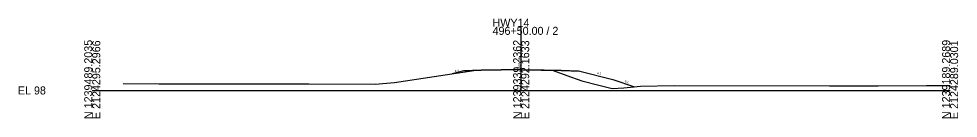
# Model space of a CAD drawing. Extents: x -26 to 303, y -10 to 11521.
# Drawn here: x -25.7 to 302.8, y 7990.3 to 8025 of the extents above; entities that cross this region are included whole.
import ezdxf

# ---------------------------------------------------------------- set-up
doc = ezdxf.new("R2010")
doc.units = 0
for name, color, linetype in [('XS_CELL', 7, 'Continuous'), ('XS_P_FINISHED_GRADE', 7, 'Continuous'), ('XS_P_SUBGRADE_GRANULAR', 7, 'Continuous'), ('XS_P_SUBGRADE_LEVELING', 7, 'Continuous'), ('XS_P_TX_FS_BS', 7, 'Continuous'), ('XS_X_GROUND', 7, 'Continuous'), ('XS_X_GROUND_TX', 7, 'Continuous')]:
    doc.layers.add(name, color=color, linetype=linetype)

msp = doc.modelspace()

# ---------------------------------------------------------------- linework, layer by layer
at = {"layer": 'XS_CELL'}
for p, q in [((150, 8000), (150, 8022.23)), ((0, 8000), (150, 8000)), ((150, 8000), (300, 8000))]:
    msp.add_line(p, q, dxfattribs=at)
at = {"layer": 'XS_P_FINISHED_GRADE'}
for p, q in [((130, 8006.83), (125.81, 8005.79)), ((136, 8007.07), (130, 8006.83)), ((150, 8007.35), (136, 8007.07)), ((150, 8007.35), (164, 8007.07)), ((164, 8007.07), (170, 8006.83)), ((170, 8006.83), (182, 8003.83)), ((182, 8003.83), (189.69, 8001.27))]:
    msp.add_line(p, q, dxfattribs=at)
at = {"layer": 'XS_P_SUBGRADE_GRANULAR'}
for p, q in [((136, 8006.95), (129.4, 8006.69)), ((164, 8006.95), (170.6, 8006.69))]:
    msp.add_line(p, q, dxfattribs=at)
at = {"layer": 'XS_P_SUBGRADE_LEVELING'}
for p, q in [((150, 8007.23), (136, 8006.95)), ((136, 8006.95), (136, 8007.07)), ((150, 8007.23), (164, 8006.95)), ((164, 8006.95), (164, 8007.07))]:
    msp.add_line(p, q, dxfattribs=at)
at = {"layer": 'XS_X_GROUND'}
for p, q in [((105.7, 8002.78), (133.49, 8006.93)), ((133.49, 8006.93), (136.11, 8007.16)), ((136.11, 8007.16), (138.86, 8007.22)), ((138.86, 8007.22), (147.66, 8007.41)), ((147.66, 8007.41), (150, 8007.35)), ((150, 8007.35), (156.52, 8007.2)), ((156.52, 8007.2), (158.09, 8007.15)), ((158.09, 8007.15), (158.6, 8007.11)), ((158.6, 8007.11), (161.18, 8006.94)), ((161.18, 8006.94), (166.02, 8005.26)), ((166.02, 8005.26), (171.24, 8003.41)), ((171.24, 8003.41), (177.13, 8001.82)), ((10.81, 8002.38), (23.3, 8002.34)), ((23.3, 8002.34), (26.44, 8002.32)), ((26.44, 8002.32), (47.26, 8002.35)), ((47.26, 8002.35), (75.73, 8002.31)), ((75.73, 8002.31), (98.97, 8002.21)), ((98.97, 8002.21), (105.7, 8002.78)), ((177.13, 8001.82), (181.8, 8000.64)), ((181.8, 8000.64), (185.96, 8000.95)), ((185.96, 8000.95), (191.71, 8001.44)), ((191.71, 8001.44), (203.52, 8001.72)), ((203.52, 8001.72), (257.79, 8001.6)), ((257.79, 8001.6), (274.82, 8001.65)), ((274.82, 8001.65), (291.75, 8001.71)), ((291.75, 8001.71), (300, 8001.7))]:
    msp.add_line(p, q, dxfattribs=at)

# ---------------------------------------------------------------- texts
at = {"layer": 'XS_CELL'}
for s, p in [('HWY14', (140, 8022.23)), ('496+50.00 / 2', (140, 8019.43)), ('EL 98', (-26, 7998.6))]:
    msp.add_text(s, height=2.8, dxfattribs=at).set_placement(p)
for s, p in [('N 1239489.2035', (0, 7990)), ('E 2124295.2966', (2.8, 7990)), ('N 1239339.2362', (150, 7990)), ('E 2124292.1633', (152.8, 7990)), ('N 1239189.2689', (300, 7990)), ('E 2124289.0301', (302.8, 7990))]:
    msp.add_text(s, height=2.8, rotation=90, dxfattribs=at).set_placement(p)
at = {"layer": 'XS_P_TX_FS_BS'}
for s, rotation, p in [('4:1', 14.0362, (126.88, 8006.23)), ('4:1', 345.9638, (176.44, 8005.76)), ('3:1', 341.5651, (186.02, 8002.86))]:
    msp.add_text(s, height=0.8, rotation=rotation, dxfattribs=at).set_placement(p)
at = {"layer": 'XS_X_GROUND_TX'}
msp.add_text('105.35', height=1, rotation=90, dxfattribs=at).set_placement((150, 8007.45))

doc.saveas('drawing.dxf')
